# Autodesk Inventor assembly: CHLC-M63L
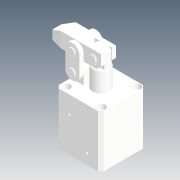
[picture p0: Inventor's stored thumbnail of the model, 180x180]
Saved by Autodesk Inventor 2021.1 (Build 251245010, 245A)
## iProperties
Created: 2019-04
Part Number: CHLC-M63L
Description: STEP AP214
Document SubType Name: Assembly
Designer: user
Title: chlc-m63_asm-L.STEP
Revision Number: ÈÎºÎ
Sending System: SolidWorks 2016
Preprocessor: SwSTEP 2.0
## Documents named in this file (10)
- D:\Vault_2016\Projekty\Clamptek\Hydraulic\CHLC\CHLC-63\Inventor\CHLC-M63L\CHLC-M63L.iam
- D:\Vault_2016\Projekty\Clamptek\Hydraulic\CHLC\CHLC-63\Inventor\CHLC-M63L\CHLC-M63-±¾Ìå.ipt
- D:\Vault_2016\Projekty\Clamptek\Hydraulic\CHLC\CHLC-63\Inventor\CHLC-M63L\CHLC-M63-͹̨00.ipt
- D:\Vault_2016\Projekty\Clamptek\Hydraulic\CHLC\CHLC-63\Inventor\CHLC-M63L\CHLC-63-01.ipt
- D:\Vault_2016\Projekty\Clamptek\Hydraulic\CHLC\CHLC-63\Inventor\CHLC-M63L\CHLC-63-02.ipt
- D:\Vault_2016\Projekty\Clamptek\Hydraulic\CHLC\CHLC-63\Inventor\CHLC-M63L\CHLC-63-03.ipt
- D:\Vault_2016\Projekty\Clamptek\Hydraulic\CHLC\CHLC-63\Inventor\CHLC-M63L\CHLC-63-04.ipt
- D:\Vault_2016\Projekty\Clamptek\Hydraulic\CHLC\CHLC-63\Inventor\CHLC-M63L\CHLC-63-05.ipt
- D:\Vault_2016\Projekty\Clamptek\Hydraulic\CHLC\CHLC-63\Inventor\CHLC-M63L\CHLC-63-07.ipt
- D:\Vault_2016\Projekty\Clamptek\Hydraulic\CHLC\CHLC-63\Inventor\CHLC-M63L\M6LS_1.ipt
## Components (17 placed, 17 different names)
1. CHLC-M63-±¾Ìå_1
2. CHLC-M63-͹̨00_2
3. CHLC-63-01_3
4. CHLC-63-02_4
5. CHLC-63-03_5
6. CHLC-63-04_6
7. CHLC-63-05_7
8. CHLC-63-07_8
9. CHLC-63-04_9
10. CHLC-63-07_10
11. CHLC-63-03_11
12. CHLC-63-07_12
13. CHLC-63-07_13
14. CHLC-63-07_14
15. M6LS_1_15
16. M6LS_1_16
17. CHLC-63-07_17
